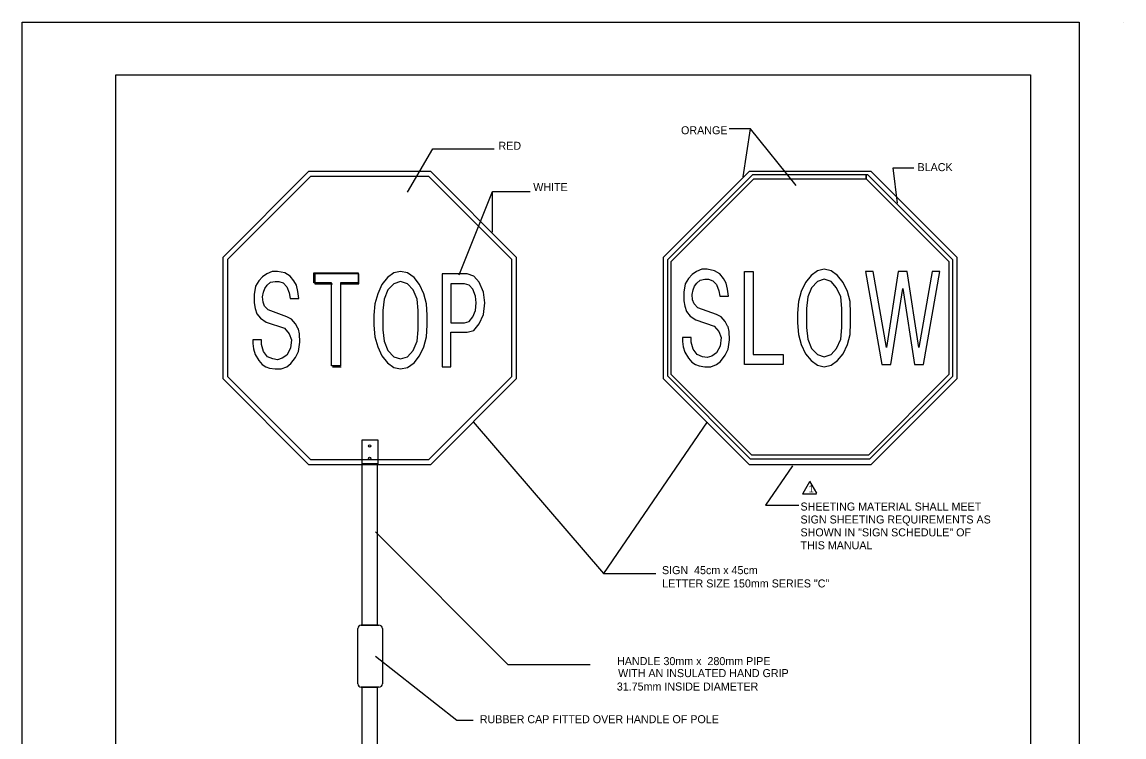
# Model space of a CAD drawing. Extents: x -16491 to -16265, y 453039 to 453318.
# Drawn here: x -16490.6 to -16265.5, y 453171.9 to 453317.9 of the extents above; entities that cross this region are included whole.
import ezdxf

# ---------------------------------------------------------------- set-up
doc = ezdxf.new("R2010")
doc.units = 0
for name, color, linetype in [('Level 1', 7, 'Continuous'), ('Level 44', 7, 'Continuous'), ('Level 5', 7, 'Continuous'), ('Level 60', 7, 'Continuous'), ('Level 63', 7, 'Continuous')]:
    doc.layers.add(name, color=color, linetype=linetype)

msp = doc.modelspace()

# ---------------------------------------------------------------- linework, layer by layer
at = {"layer": 'Level 1'}
for p, q in [((-16341.75, 453296.07), (-16346.13, 453296.07)), ((-16343.26, 453286.28), (-16341.75, 453296.07)), ((-16332.39, 453284.47), (-16341.75, 453296.07)), ((-16411.81, 453283.11), (-16406.68, 453292)), ((-16406.68, 453292), (-16394.14, 453292)), ((-16317.17, 453287.39), (-16299.62, 453269.84)), ((-16312.61, 453288.08), (-16308.38, 453288.08)), ((-16311.7, 453280.85), (-16312.61, 453288.08)), ((-16341.36, 453286.64), (-16358.71, 453269.28)), ((-16357.94, 453268.96), (-16341.04, 453285.87)), ((-16318.11, 453286.64), (-16341.36, 453286.64)), ((-16341.04, 453285.87), (-16318.11, 453285.86)), ((-16318.11, 453285.86), (-16318.11, 453286.64)), ((-16317.79, 453286.64), (-16318.11, 453286.64)), ((-16318.11, 453286.64), (-16318.11, 453285.86)), ((-16318.11, 453285.86), (-16301.22, 453268.98)), ((-16300.45, 453269.3), (-16317.79, 453286.64)), ((-16401.24, 453266.24), (-16394.44, 453283.26)), ((-16394.44, 453283.26), (-16386.74, 453283.26)), ((-16394.44, 453274.98), (-16394.44, 453283.26)), ((-16358.71, 453269.28), (-16358.71, 453245.59)), ((-16357.94, 453245.91), (-16357.94, 453268.96)), ((-16301.22, 453268.98), (-16301.22, 453245.89)), ((-16300.45, 453245.57), (-16300.45, 453269.3)), ((-16430.98, 453266.66), (-16421.93, 453266.66)), ((-16430.98, 453264.62), (-16430.98, 453266.66)), ((-16421.74, 453266.46), (-16430.78, 453266.46)), ((-16430.78, 453266.46), (-16430.78, 453264.42)), ((-16421.93, 453266.66), (-16421.93, 453264.62)), ((-16421.74, 453264.42), (-16421.74, 453266.46)), ((-16343, 453266.91), (-16341.19, 453266.91)), ((-16343, 453247.94), (-16343, 453266.91)), ((-16343, 453266.91), (-16341.19, 453266.91)), ((-16341.19, 453266.91), (-16341.19, 453249.98)), ((-16427.36, 453264.62), (-16430.98, 453264.62)), ((-16430.78, 453264.42), (-16427.16, 453264.42)), ((-16427.36, 453247.69), (-16427.36, 453264.62)), ((-16421.93, 453264.62), (-16425.55, 453264.62)), ((-16425.55, 453264.62), (-16425.55, 453247.69)), ((-16425.35, 453264.42), (-16421.74, 453264.42)), ((-16341.19, 453249.98), (-16335.1, 453249.98)), ((-16335.1, 453249.98), (-16335.1, 453247.94)), ((-16425.55, 453247.69), (-16427.36, 453247.69)), ((-16427.16, 453247.49), (-16425.35, 453247.49)), ((-16335.1, 453247.94), (-16343, 453247.94)), ((-16358.71, 453245.59), (-16341.8, 453228.67)), ((-16341.48, 453229.45), (-16357.94, 453245.91)), ((-16301.22, 453245.89), (-16317.67, 453229.45)), ((-16317.35, 453228.67), (-16300.45, 453245.57)), ((-16398.38, 453236.26), (-16371.78, 453205.29)), ((-16350.62, 453236.26), (-16371.78, 453205.29)), ((-16341.8, 453228.67), (-16317.35, 453228.67)), ((-16317.67, 453229.45), (-16341.48, 453229.45)), ((-16333.18, 453227.27), (-16338.67, 453219.23)), ((-16338.67, 453219.23), (-16331.86, 453219.23)), ((-16418.4, 453213.74), (-16391.33, 453186.67)), ((-16371.78, 453205.29), (-16361.12, 453205.29)), ((-16421.27, 453194.71), (-16417.67, 453194.71)), ((-16421.11, 453194.73), (-16418.4, 453194.73)), ((-16421.11, 453194.73), (-16418.01, 453194.73)), ((-16421.97, 453182.73), (-16421.97, 453194.01)), ((-16416.97, 453194.01), (-16416.97, 453182.73)), ((-16418.4, 453188.38), (-16401.73, 453175.33)), ((-16391.33, 453186.67), (-16374.52, 453186.67)), ((-16417.67, 453182.03), (-16421.27, 453182.03)), ((-16401.73, 453175.33), (-16398.4, 453175.33))]:
    msp.add_line(p, q, dxfattribs=at)
for points in [[(-16431.97, 453227.48), (-16449.51, 453245.03), (-16449.51, 453269.84), (-16431.97, 453287.39), (-16407.15, 453287.39), (-16389.61, 453269.84), (-16389.61, 453245.03), (-16407.15, 453227.48)], [(-16341.98, 453287.39), (-16317.17, 453287.39), (-16299.62, 453269.84), (-16299.62, 453245.03), (-16317.17, 453227.48), (-16341.98, 453227.48), (-16359.52, 453245.03), (-16359.52, 453269.84)], [(-16448.54, 453269.44), (-16431.56, 453286.42), (-16407.56, 453286.42), (-16390.58, 453269.44), (-16390.58, 453245.43), (-16407.56, 453228.45), (-16431.56, 453228.45), (-16448.54, 453245.43)], [(-16421.11, 453232.57), (-16417.92, 453232.57), (-16417.92, 453227.63), (-16421.11, 453227.63)], [(-16421.11, 453227.63), (-16418.01, 453227.63), (-16418.01, 453194.73), (-16421.11, 453194.73)], [(-16421.11, 453182.03), (-16418.01, 453182.03), (-16418.01, 453067.55), (-16421.11, 453067.55)]]:
    msp.add_lwpolyline(points, close=True, dxfattribs=at)
for points in [[(-16443.45, 453252.98), (-16443.45, 453252.19), (-16443.26, 453251.1), (-16442.97, 453250), (-16442.21, 453248.74), (-16441.54, 453247.96), (-16440.78, 453247.49), (-16440.02, 453247.18), (-16438.88, 453247.02), (-16437.64, 453247.02), (-16436.5, 453247.49), (-16435.64, 453248.12), (-16434.69, 453249.37), (-16434.12, 453250.62), (-16433.83, 453252.51), (-16433.92, 453254.23), (-16434.12, 453255.17), (-16434.21, 453255.33), (-16434.69, 453256.27), (-16435.54, 453257.21), (-16436.5, 453257.68), (-16440.31, 453259.09), (-16441.07, 453259.88), (-16441.35, 453260.66), (-16441.45, 453261.76), (-16441.26, 453262.7), (-16440.97, 453263.48), (-16440.5, 453264.11), (-16439.83, 453264.74), (-16438.88, 453264.89), (-16438.11, 453264.89), (-16437.26, 453264.58), (-16436.5, 453263.79), (-16436.02, 453262.54), (-16435.83, 453261.44), (-16434.02, 453261.44), (-16434.21, 453262.85), (-16434.49, 453264.11), (-16435.07, 453265.05), (-16435.83, 453265.99), (-16436.88, 453266.62), (-16438.4, 453266.93), (-16439.45, 453266.93), (-16440.59, 453266.46), (-16441.45, 453265.83), (-16442.21, 453265.05), (-16442.88, 453263.95), (-16443.16, 453262.23), (-16443.16, 453260.5), (-16442.97, 453259.4), (-16442.59, 453258.31), (-16441.83, 453257.37), (-16440.69, 453256.58), (-16436.97, 453255.33), (-16436.02, 453254.23), (-16435.54, 453252.98), (-16435.73, 453251.25), (-16436.5, 453249.84), (-16437.45, 453249.21), (-16438.4, 453248.9), (-16439.35, 453249.06), (-16440.4, 453249.53), (-16441.26, 453250.62), (-16441.64, 453252.04), (-16441.64, 453252.98), (-16443.45, 453252.98)], [(-16407.83, 453257.99), (-16407.93, 453260.35), (-16408.5, 453262.38), (-16409.35, 453264.26), (-16410.5, 453265.67), (-16411.83, 453266.62), (-16413.26, 453266.93), (-16414.59, 453266.62), (-16415.93, 453265.67), (-16417.07, 453264.26), (-16417.92, 453262.38), (-16418.5, 453260.35), (-16418.69, 453257.99), (-16418.69, 453255.95), (-16418.5, 453253.6), (-16417.92, 453251.57), (-16417.07, 453249.69), (-16415.93, 453248.27), (-16414.59, 453247.34), (-16413.26, 453247.02), (-16411.83, 453247.34), (-16410.5, 453248.27), (-16409.35, 453249.69), (-16408.5, 453251.57), (-16407.93, 453253.6), (-16407.83, 453255.95), (-16407.83, 453257.99)], [(-16402.97, 453254.54), (-16399.64, 453254.54), (-16398.31, 453254.86), (-16397.16, 453256.27), (-16396.31, 453258.15), (-16396.02, 453260.5), (-16396.31, 453262.7), (-16397.16, 453264.74), (-16398.31, 453265.99), (-16399.64, 453266.46), (-16404.78, 453266.46), (-16404.78, 453247.49), (-16402.97, 453247.49), (-16402.97, 453254.54)], [(-16355.67, 453253.43), (-16355.67, 453252.64), (-16355.48, 453251.55), (-16355.19, 453250.45), (-16354.43, 453249.2), (-16353.76, 453248.41), (-16353, 453247.94), (-16352.24, 453247.63), (-16351.1, 453247.47), (-16349.86, 453247.47), (-16348.71, 453247.94), (-16347.86, 453248.57), (-16346.91, 453249.82), (-16346.33, 453251.08), (-16346.05, 453252.96), (-16346.14, 453254.68), (-16346.33, 453255.62), (-16346.43, 453255.78), (-16346.91, 453256.72), (-16347.76, 453257.66), (-16348.71, 453258.13), (-16352.52, 453259.54), (-16353.29, 453260.33), (-16353.57, 453261.11), (-16353.67, 453262.21), (-16353.48, 453263.15), (-16353.19, 453263.93), (-16352.71, 453264.56), (-16352.05, 453265.18), (-16351.1, 453265.34), (-16350.34, 453265.34), (-16349.48, 453265.03), (-16348.71, 453264.24), (-16348.24, 453262.99), (-16348.05, 453261.89), (-16346.24, 453261.89), (-16346.43, 453263.3), (-16346.71, 453264.56), (-16347.29, 453265.5), (-16348.05, 453266.44), (-16349.1, 453267.07), (-16350.62, 453267.38), (-16351.67, 453267.38), (-16352.81, 453266.91), (-16353.67, 453266.28), (-16354.43, 453265.5), (-16355.1, 453264.4), (-16355.38, 453262.68), (-16355.38, 453260.95), (-16355.19, 453259.86), (-16354.81, 453258.76), (-16354.05, 453257.82), (-16352.9, 453257.03), (-16349.19, 453255.78), (-16348.24, 453254.68), (-16347.76, 453253.43), (-16347.95, 453251.7), (-16348.71, 453250.29), (-16349.67, 453249.67), (-16350.62, 453249.35), (-16351.57, 453249.51), (-16352.62, 453249.98), (-16353.48, 453251.08), (-16353.86, 453252.49), (-16353.86, 453253.43), (-16355.67, 453253.43)], [(-16321.29, 453258.45), (-16321.38, 453260.79), (-16321.95, 453262.83), (-16322.81, 453264.71), (-16323.95, 453266.12), (-16325.29, 453267.07), (-16326.72, 453267.38), (-16328.05, 453267.07), (-16329.38, 453266.12), (-16330.52, 453264.71), (-16331.38, 453262.83), (-16331.95, 453260.79), (-16332.14, 453258.45), (-16332.14, 453256.41), (-16331.95, 453254.05), (-16331.38, 453252.02), (-16330.52, 453250.14), (-16329.38, 453248.72), (-16328.05, 453247.78), (-16326.72, 453247.47), (-16325.29, 453247.78), (-16323.95, 453248.72), (-16322.81, 453250.14), (-16321.95, 453252.02), (-16321.38, 453254.05), (-16321.29, 453256.41), (-16321.29, 453258.45)], [(-16313.95, 453251.39), (-16316.72, 453266.91), (-16318.24, 453266.91), (-16314.91, 453247.94), (-16313.1, 453247.94), (-16310.62, 453263.46), (-16308.24, 453247.94), (-16306.43, 453247.94), (-16303.1, 453266.91), (-16304.62, 453266.91), (-16307.38, 453251.39), (-16309.76, 453266.91), (-16311.57, 453266.91), (-16313.95, 453251.39)], [(-16409.64, 453258.93), (-16409.83, 453261.29), (-16410.69, 453263.17), (-16411.83, 453264.42), (-16413.26, 453264.89), (-16414.59, 453264.42), (-16415.83, 453263.17), (-16416.59, 453261.29), (-16416.88, 453258.93), (-16416.88, 453255.02), (-16416.59, 453252.67), (-16415.83, 453250.78), (-16414.59, 453249.53), (-16413.26, 453249.06), (-16411.83, 453249.53), (-16410.69, 453250.78), (-16409.83, 453252.67), (-16409.64, 453255.02), (-16409.64, 453258.93)], [(-16402.97, 453264.42), (-16402.97, 453256.42), (-16400.21, 453256.42), (-16399.26, 453256.74), (-16398.5, 453257.68), (-16397.93, 453258.93), (-16397.83, 453260.5), (-16397.93, 453261.91), (-16398.5, 453263.33), (-16399.26, 453264.11), (-16400.21, 453264.42), (-16402.97, 453264.42)], [(-16323.1, 453259.38), (-16323.29, 453261.73), (-16324.15, 453263.62), (-16325.29, 453264.87), (-16326.72, 453265.34), (-16328.05, 453264.87), (-16329.29, 453263.62), (-16330.05, 453261.73), (-16330.34, 453259.38), (-16330.34, 453255.46), (-16330.05, 453253.11), (-16329.29, 453251.23), (-16328.05, 453249.98), (-16326.72, 453249.51), (-16325.29, 453249.98), (-16324.15, 453251.23), (-16323.29, 453253.11), (-16323.1, 453255.46), (-16323.1, 453259.38)]]:
    msp.add_lwpolyline(points, dxfattribs=at)
for centre in [(-16419.56, 453231.3), (-16419.56, 453231.3), (-16419.56, 453228.76), (-16419.56, 453228.76)]:
    msp.add_circle(centre, 0.242, dxfattribs=at)
for centre, start, end in [((-16421.27, 453194.01), 90, 180), ((-16417.67, 453194.01), 0, 90), ((-16421.27, 453182.73), 180, 270), ((-16417.67, 453182.73), 270, 0)]:
    msp.add_arc(centre, 0.7, start, end, dxfattribs=at)
at = {"layer": 'Level 60'}
for p, q in [((-16490.58, 453317.86), (-16490.58, 453317.86)), ((-16265.45, 453317.86), (-16265.45, 453317.86))]:
    msp.add_line(p, q, dxfattribs=at)
for points in [[(-16490.58, 453317.86), (-16274.58, 453317.86), (-16274.58, 453038.86), (-16490.58, 453038.86)], [(-16471.45, 453307.06), (-16284.58, 453307.06), (-16284.58, 453049.67), (-16471.45, 453049.67)]]:
    msp.add_lwpolyline(points, close=True, dxfattribs=at)
at = {"layer": 'Level 63'}
for points in [[(-16329.69, 453224), (-16331.08, 453221.57)], [(-16328.21, 453221.65), (-16329.6, 453224.08)], [(-16331.08, 453221.57), (-16331.11, 453221.53), (-16328.27, 453221.53), (-16328.29, 453221.57)]]:
    msp.add_lwpolyline(points, dxfattribs=at)

# ---------------------------------------------------------------- texts
at = {"layer": 'Level 1'}
for s, height, p in [('ORANGE', 1.635, (-16355.94, 453294.95)), ('RED', 1.635, (-16393.24, 453291.78)), ('BLACK', 1.635, (-16307.63, 453287.42)), ('WHITE', 1.635, (-16386.14, 453283.35)), ('SHEETING MATERIAL SHALL MEET', 1.635, (-16331.54, 453218.11)), ('SIGN SHEETING REQUIREMENTS AS', 1.635, (-16331.54, 453215.47)), ('SHOWN IN "SIGN SCHEDULE" OF', 1.635, (-16331.54, 453212.84)), ('THIS MANUAL', 1.635, (-16331.54, 453210.2)), ('SIGN  45cm x 45cm', 1.635, (-16359.84, 453205.12)), ('LETTER SIZE 150mm SERIES "C" ', 1.635, (-16359.78, 453202.41)), ('HANDLE 30mm x  280mm PIPE', 1.6347, (-16369.01, 453186.55)), ('WITH AN INSULATED HAND GRIP', 1.6347, (-16368.8, 453184.1)), ('RUBBER CAP FITTED OVER HANDLE OF POLE', 1.6352, (-16397.06, 453174.69))]:
    msp.add_text(s, height=height, dxfattribs=at).set_placement(p)
at = {"layer": 'Level 44'}
msp.add_text('1', height=1.45, rotation=360, dxfattribs=at).set_placement((-16329.9, 453221.8))
at = {"layer": 'Level 5'}
msp.add_text('31.75mm INSIDE DIAMETER', height=1.6347, rotation=360, dxfattribs=at).set_placement((-16369.07, 453181.36))

doc.saveas('drawing.dxf')
